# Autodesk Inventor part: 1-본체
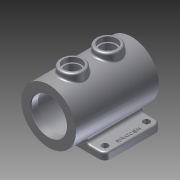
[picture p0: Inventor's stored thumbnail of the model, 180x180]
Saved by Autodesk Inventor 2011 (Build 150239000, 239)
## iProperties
Created: 2014-12
Part Number: 1-본체
Document SubType Name: Modeling
Designer: user
Density: 1 g/cm^3
Mass: 476.915 g
Surface Area: 1041.85 cm^2
Volume: 476.915 cm^3
Author: user
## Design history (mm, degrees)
sketch "스케치1"
  geometry: L1 (-65, 47.5)-(65, 47.5); L2 (65, 47.5)-(65, -47.5); L3 (65, -47.5)-(-65, -47.5); L4 (-65, -47.5)-(-65, 47.5); 3 further points
  constraints: 8 end point, 2 midpoint, 2 parallel, 1 horizontal, 1 horizontal alignment, 1 perpendicular, 1 vertical alignment
  dimensions: "d0" = 130 distance of L2.end L3.end; "d1" = 95 distance of L1.end L2.end
extrude "돌출1" new body sketch "스케치1" distance "d2" = 12; taper "d3" = 0 deg
node "작업 평면1"
sketch "스케치2"
  geometry: L1 (0, 0)-(130, 0) reference; C1 r 46 at (65, -50); 1 further point
  constraints: 1 centre point, 1 vertical alignment
  dimensions: "d5" = 92 diameter of C1; "d6" = 50 distance from line of L1 C1.centre
extrude "돌출2" join sketch "스케치2" distance "d7" = 140; taper "d8" = 0 deg
sketch "스케치3"
  geometry: C1 r 46 at (0, 0) reference; C2 r 30 at (0, 0); 1 further point
  constraints: 1 centre point, 1 coincident
  dimensions: "d9" = 60 diameter of C2
extrude "돌출3" cut sketch "스케치3" distance "d10" = 12; taper "d11" = 0 deg
sketch "스케치4"
  geometry: C1 r 30 at (0, 0) reference; C2 r 37.5 at (0, 0); 1 further point
  constraints: 1 centre point, 1 coincident
  dimensions: "d12" = 75 diameter of C2
extrude "돌출4" cut sketch "스케치4" distance "d13" = 116; taper "d14" = 0 deg
sketch "스케치5"
  geometry: C1 r 46 at (0, 0) reference; C2 r 30 at (0, 0); 1 further point
  constraints: 1 centre point, 1 coincident
  dimensions: "d15" = 60 diameter of C2
extrude "돌출5" cut sketch "스케치5" distance "d16" = 12; taper "d17" = 0 deg
sketch "스케치6"
  geometry: L1 (0, 0)-(28.284, 28.284); L2 (0, 0)-(0, 40); C1 r 30 at (0, 0) reference; 2 further points
  constraints: 4 end point, 1 coincident, 1 vertical
  dimensions: "d27" = 40 distance of L1.start L2.end; "d28" = 45 deg angle of L1 L2
hole "Hole2" sketch "스케치6" at (28.284, 28.284) diameter "d29" = 3.242; stored, may be unused: countersink angle "d33" = 90 deg, drill point angle "d35" = 118 deg; dims "d30" = 8, "d31" = 4, "d32" = 2, "d34" = 10
node "작업 평면2"
node "작업 평면3"
sketch "스케치7"
  geometry: L1 (-65, 47.5)-(-25.923, 47.5) reference; L2 (46, -77.5)-(-46, -77.5) reference; L3 (-46, 62.5)-(46, 62.5) reference; C1 r 20 at (0, 22.5); C2 r 20 at (0, -37.5); 2 further points
  constraints: 2 centre point, 2 vertical alignment, 1 midpoint
  dimensions: "d40" = 40 diameter of C1; "d42" = 40 diameter of C2; "d43" = 40 distance from line of C2.centre L2; "d44" = 40 distance from line of L3 C1.centre
extrude "돌출6" join sketch "스케치7" stored distance "d45" = 12; taper "d46" = 0 deg
sketch "스케치8"
  geometry: C1 r 20 at (0, 0) reference; C2 r 15 at (0, 0); 1 further point
  constraints: 1 centre point, 1 coincident
  dimensions: "d47" = 30 diameter of C2
extrude "돌출7" cut sketch "스케치8" distance "d48" = 8; taper "d49" = 0 deg
sketch "스케치9"
  geometry: C1 r 15 at (0, 0) reference; C2 r 12.5 at (0, 0); 1 further point
  constraints: 1 centre point, 1 coincident
  dimensions: "d50" = 25 diameter of C2
extrude "돌출8" cut sketch "스케치9" stored distance "d51" = 8; taper "d52" = 0 deg
chamfer "모따기1" distance "d53" = 1; stored, may be unused: second distance "d54" = 2, angle "d55" = 45 deg
fillet "모깎기1" dims "d56" = 10
sketch "스케치11"
  geometry: L1 (55, -47.5)-(25.923, -47.5) reference; L2 (65, 37.5)-(65, -37.5) reference; C1 r 5.5 at (52.5, -35); 1 further point
  constraints: 1 centre point
  dimensions: "d57" = 11 diameter of C1; "d58" = 12.5 distance from line of L2 C1.centre; "d59" = 12.5 distance from line of L1 C1.centre
extrude "돌출9" cut sketch "스케치11" stored distance "d60" = 8; taper "d61" = 0 deg
node "작업 평면4"
node "작업 평면5"
sketch "스케치12"
  geometry: L1 (65, 37.5)-(65, -37.5) reference; C1 r 5.5 at (52.5, -35) reference; 2 further points
  constraints: 1 other
  dimensions: "d62" = 8 distance from line of L1 point (57, 0); "d63" = 35 vertical distance of C1.centre point (57, 0)
fillet "모깎기2" dims "d66" = 5
fillet "모깎기3" dims "d67" = 3
fillet "모깎기4" dims "d68" = 3
fillet "모깎기5" dims "d69" = 3
fillet "모깎기6" dims "d70" = 2
feature "엠보싱1" dims "d0" = 130, "d1" = 95, "d71" = 1, "d72" = 0
node "솔리드1"
pattern_circular "원형 패턴1" dims angle "d37" = 360 deg
mirror "대칭1"
mirror "대칭2"
mirror "대칭3"
mirror "대칭4"
other parameters: "d4" = 15, "d39" = -106
